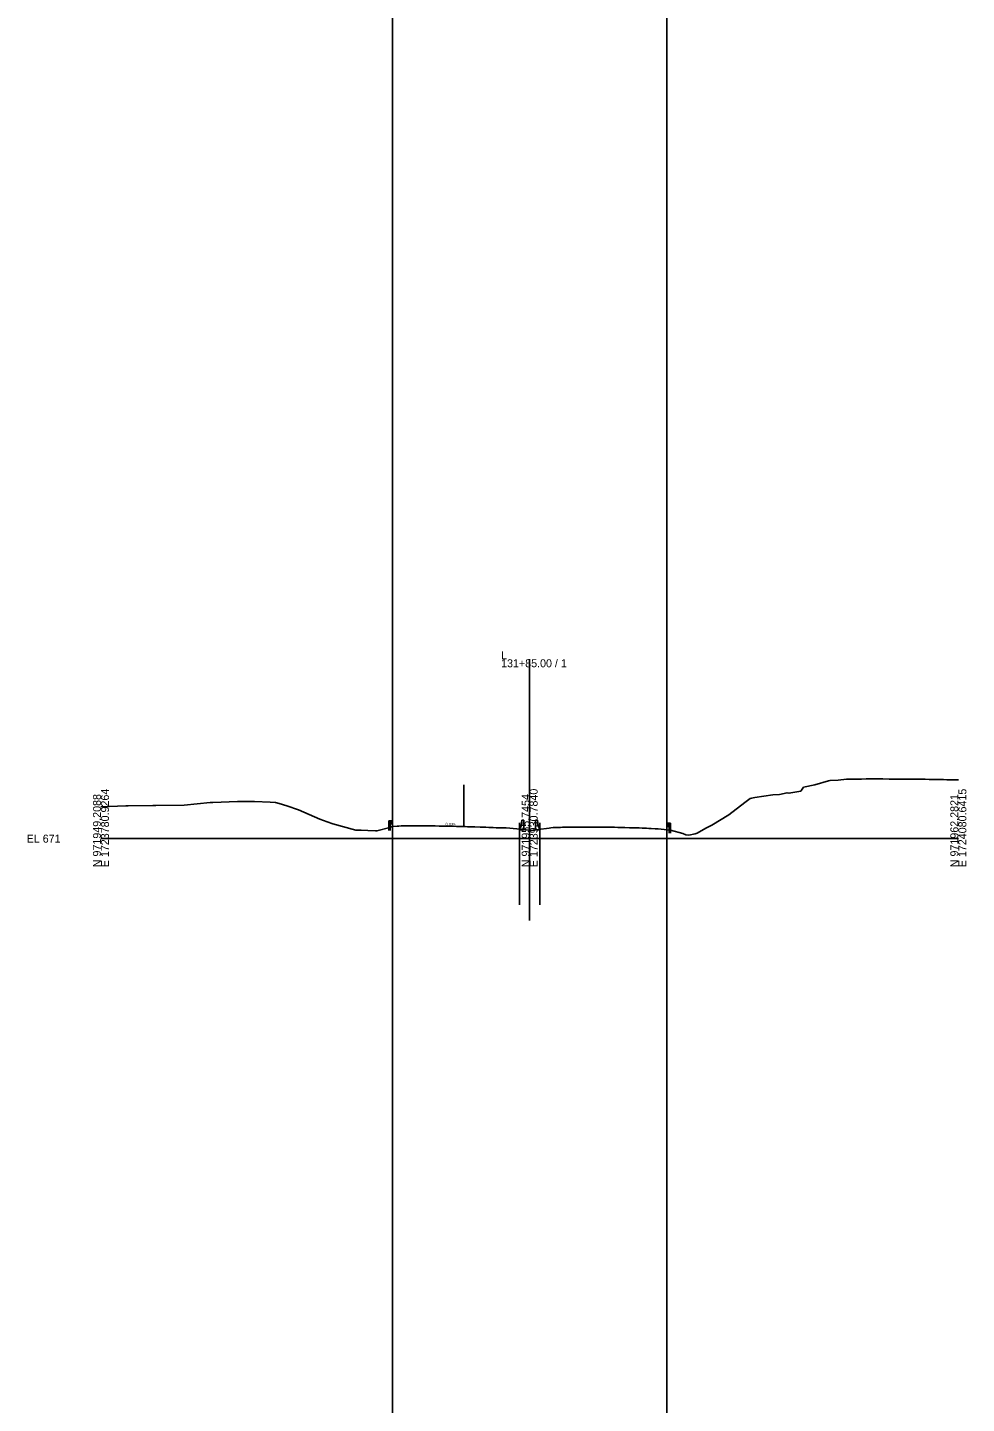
# Model space of a CAD drawing. Extents: x -26 to 303, y -29 to 15026.
# Drawn here: x -25.7 to 302.8, y 7802.3 to 8283.9 of the extents above; entities that cross this region are included whole.
import ezdxf

# ---------------------------------------------------------------- set-up
doc = ezdxf.new("R2010")
doc.units = 0
for name, color, linetype in [('Exist Cross Section Cell', 7, 'Continuous'), ('Exist XS Center Line Elevation Label', 7, 'Continuous'), ('Exist XS Ground Line', 7, 'Continuous'), ('Prop XS Ditch Standard Text', 7, 'Continuous'), ('Scratch_Level_0', 7, 'Continuous'), ('Typical Guardrail CELL', 7, 'Continuous'), ('Typical Median Barrier CELL', 7, 'Continuous')]:
    doc.layers.add(name, color=color, linetype=linetype)

msp = doc.modelspace()

# ---------------------------------------------------------------- linework, layer by layer
at = {"layer": 'Exist Cross Section Cell'}
for p, q in [((150, 8000), (150, 8062.78)), ((0, 8000), (150, 8000)), ((150, 8000), (300, 8000))]:
    msp.add_line(p, q, dxfattribs=at)
at = {"layer": 'Exist XS Ground Line'}
msp.add_lwpolyline([(0, 8011.17), (8.68, 8011.44), (9.09, 8011.46), (9.47, 8011.46), (18.12, 8011.59), (19.15, 8011.61), (29.11, 8011.66), (38.24, 8012.61), (39.12, 8012.63), (47.83, 8012.96), (49.13, 8013.04), (53.7, 8012.97), (59.16, 8012.8), (61.04, 8012.66), (62.31, 8012.29), (65.08, 8011.5), (69.15, 8010.08), (76.61, 8006.79), (79.16, 8005.85), (81.19, 8005.19), (89.21, 8002.92), (91.1, 8002.92), (93.33, 8002.9), (96.01, 8002.76), (96.57, 8002.72), (101.05, 8003.9), (101.93, 8004.25), (103.62, 8004.35), (104.28, 8004.41), (105.08, 8004.5), (105.87, 8004.53), (106.55, 8004.53), (108.29, 8004.53), (109.94, 8004.52), (110.79, 8004.52), (111.33, 8004.52), (112.09, 8004.5), (113.3, 8004.48), (114.73, 8004.46), (115.8, 8004.45), (116.97, 8004.43), (118.3, 8004.42), (119.52, 8004.39), (120.78, 8004.36), (122.14, 8004.34), (123.07, 8004.32), (124.35, 8004.28), (125.77, 8004.24), (127.39, 8004.2), (128.28, 8004.18), (130.02, 8004.12), (130.78, 8004.1), (132.66, 8004.04), (133.3, 8004.01), (134.67, 8003.96), (135.72, 8003.92), (137.21, 8003.88), (138.31, 8003.84), (138.66, 8003.83), (140.91, 8003.77), (141.83, 8003.74), (148, 8003.17), (149.65, 8003.02), (150.03, 8002.99), (150.65, 8002.89), (151.41, 8003.02), (152.99, 8003.23), (156.82, 8003.72), (157.42, 8003.79), (158.23, 8003.86), (158.67, 8003.88), (160.29, 8003.93), (160.8, 8003.95), (161.45, 8003.97), (163.32, 8004.02), (163.77, 8004.04), (164.34, 8004.06), (165.06, 8004.06), (165.83, 8004.06), (167.47, 8004.06), (168.35, 8004.06), (169.31, 8004.06), (170.86, 8004.07), (172.29, 8004.06), (173.35, 8004.06), (174.52, 8004.06), (175.85, 8004.05), (177.18, 8004.04), (178.35, 8004.01), (179.74, 8003.97), (180.83, 8003.94), (181.83, 8003.92), (183.32, 8003.88), (184.96, 8003.83), (185.82, 8003.81), (186.61, 8003.79), (188.35, 8003.74), (189.38, 8003.7), (190.85, 8003.63), (191.65, 8003.59), (192.46, 8003.54), (193.88, 8003.45), (194.97, 8003.39), (196.06, 8003.3), (197.03, 8003.21), (199.29, 8002.95), (203.56, 8001.75), (204.66, 8001.39), (205.66, 8001.27), (207.91, 8001.74), (208.59, 8001.91), (211.62, 8003.67), (213.8, 8004.75), (219.65, 8008.39), (225.29, 8012.62), (227.1, 8014), (227.66, 8014.14), (228.23, 8014.31), (228.8, 8014.38), (235.12, 8015.36), (237.43, 8015.47), (240.09, 8016.06), (240.69, 8015.89), (244.83, 8016.65), (245.82, 8017.99), (249.77, 8018.81), (254.59, 8020.22), (255.11, 8020.36), (257.98, 8020.51), (260.81, 8020.77), (266.16, 8020.86), (267.71, 8020.93), (270.51, 8020.92), (270.83, 8020.91), (271.83, 8020.9), (273.1, 8020.88), (273.52, 8020.88), (275.78, 8020.86), (276.64, 8020.85), (278.24, 8020.84), (278.58, 8020.83), (280.27, 8020.83), (280.95, 8020.83), (282.56, 8020.82), (283.46, 8020.8), (284.96, 8020.79), (285.95, 8020.79), (287.35, 8020.76), (288.44, 8020.76), (289.75, 8020.73), (290.93, 8020.72), (292.16, 8020.71), (293.44, 8020.68), (294.82, 8020.66), (295.95, 8020.64), (296.31, 8020.64), (297.82, 8020.62), (298.85, 8020.61), (299.67, 8020.6), (300, 8020.59)], dxfattribs=at)
at = {"layer": 'Scratch_Level_0'}
for p, q in [((102, 15009.56), (102, -28.7)), ((198, 15009.56), (198, -28.7)), ((127, 8018.8), (127, 8004.21)), ((127, 8004.21), (120.78, 8004.36)), ((146.46, 8005.5), (146.46, 7976.8)), ((153.54, 8005.5), (153.54, 7976.8)), ((150, 8000), (150, 7971.3)), ((150, 8000), (150, 7971.3))]:
    msp.add_line(p, q, dxfattribs=at)
at = {"layer": 'Typical Guardrail CELL'}
for p, q in [((101.18, 8006.29), (100.68, 8006.29)), ((100.68, 8006.29), (100.68, 8003.81)), ((101.18, 8003.81), (100.68, 8003.81)), ((100.68, 8003.81), (100.68, 8002.8)), ((101.18, 8006.29), (101.18, 8003.81)), ((101.18, 8006.29), (101.68, 8006.29)), ((101.18, 8005.13), (101.68, 8005.13)), ((101.18, 8003.81), (101.18, 8002.8)), ((101.68, 8006.29), (101.68, 8005.13)), ((101.68, 8006.29), (101.97, 8006.09)), ((101.68, 8005.76), (101.97, 8005.96)), ((101.68, 8005.71), (101.68, 8005.76)), ((101.68, 8005.71), (101.68, 8005.66)), ((101.68, 8005.66), (101.97, 8005.46)), ((101.68, 8005.13), (101.97, 8005.33)), ((198.32, 8005.43), (198.03, 8005.23)), ((198.32, 8004.9), (198.03, 8005.1)), ((198.32, 8004.81), (198.03, 8004.6)), ((198.32, 8004.27), (198.03, 8004.48)), ((198.82, 8005.43), (198.32, 8005.43)), ((198.32, 8005.43), (198.32, 8004.27)), ((198.32, 8004.85), (198.32, 8004.9)), ((198.32, 8004.85), (198.32, 8004.81)), ((198.82, 8004.27), (198.32, 8004.27)), ((198.82, 8005.43), (198.82, 8002.95)), ((198.82, 8005.43), (199.32, 8005.43)), ((199.32, 8005.43), (199.32, 8002.95)), ((198.82, 8002.95), (199.32, 8002.95)), ((198.82, 8002.95), (198.82, 8001.94)), ((199.32, 8002.95), (199.32, 8001.94))]:
    msp.add_line(p, q, dxfattribs=at)
for centre, start, end in [((101.92, 8006.02), 304.9888, 54.997), ((101.92, 8005.4), 304.9634, 54.9941), ((198.08, 8005.17), 125.003, 235.0112), ((198.08, 8004.54), 125.0059, 235.0366)]:
    msp.add_arc(centre, 0.0776, start, end, dxfattribs=at)
at = {"layer": 'Typical Median Barrier CELL'}
for p, q in [((146.46, 8003.52), (146.92, 8004.18)), ((147.07, 8004.57), (147.29, 8006.52)), ((147.29, 8006.52), (147.96, 8006.52)), ((147.96, 8006.52), (147.96, 8003.11)), ((152.71, 8006.52), (152.04, 8006.52)), ((152.04, 8006.52), (152.04, 8003.11)), ((152.93, 8004.57), (152.71, 8006.52)), ((153.54, 8003.52), (153.08, 8004.18)), ((146.46, 8003.11), (146.46, 8003.52)), ((147.96, 8003.11), (146.46, 8003.11)), ((152.04, 8003.11), (153.54, 8003.11)), ((153.54, 8003.11), (153.54, 8003.52))]:
    msp.add_line(p, q, dxfattribs=at)
for centre, start, end in [((146.24, 8004.66), 325.0039, 353.9447), ((153.76, 8004.66), 186.0553, 214.9961)]:
    msp.add_arc(centre, 0.833, start, end, dxfattribs=at)

# ---------------------------------------------------------------- texts
at = {"layer": 'Exist Cross Section Cell'}
for s, p in [('131+85.00 / 1', (140, 8059.98)), ('L', (140, 8062.78)), ('EL 671', (-26, 7998.6))]:
    msp.add_text(s, height=2.8, dxfattribs=at).set_placement(p)
for s, p in [('N 971949.2088', (0, 7990)), ('E 1723780.9264', (2.8, 7990)), ('N 971955.7454', (150, 7990)), ('E 1723930.7840', (152.8, 7990)), ('N 971962.2821', (300, 7990)), ('E 1724080.6415', (302.8, 7990))]:
    msp.add_text(s, height=2.8, rotation=90, dxfattribs=at).set_placement(p)
at = {"layer": 'Exist XS Center Line Elevation Label'}
msp.add_text('673.99', height=0.18, dxfattribs=at).set_placement((149.62, 8002.5))
at = {"layer": 'Prop XS Ditch Standard Text'}
msp.add_text('0.025', height=1, rotation=358.5748, dxfattribs=at).set_placement((120.57, 8004.56))

doc.saveas('drawing.dxf')
